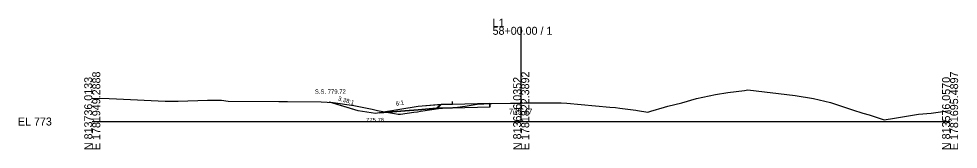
# Model space of a CAD drawing. Extents: x 5574 to 10203, y -10 to 9546.
# Drawn here: x 6574.3 to 6902.8, y 4990.3 to 5036 of the extents above; entities that cross this region are included whole.
import ezdxf

# ---------------------------------------------------------------- set-up
doc = ezdxf.new("R2010")
doc.units = 0
for name, color, linetype in [('Exist Cross Section Cell', 7, 'Continuous'), ('Exist XS Center Line Elevation Label', 7, 'Continuous'), ('Exist XS Ground Line', 7, 'Continuous'), ('Prop XS Ditch Slope Text', 7, 'Continuous'), ('Prop XS Ditch Standard Text', 7, 'Continuous'), ('Prop XS Dump Level', 7, 'Continuous'), ('Prop XS Earthwork Shape', 7, 'Continuous'), ('Prop XS EOT Tick Mark', 7, 'Continuous'), ('Prop XS Finish Grade', 7, 'Continuous'), ('Prop XS Finish Grade Earthwork', 7, 'Continuous'), ('Prop XS Finish Grade Paved Shoulder', 7, 'Continuous'), ('Prop XS Finish Grade Pavement', 7, 'Continuous'), ('Prop XS Hydro Typical Ditch Data', 7, 'Continuous'), ('Prop XS Pvmt Edge Slope', 7, 'Continuous'), ('Prop XS Side Slope Text', 7, 'Continuous'), ('Prop XS SS Elevation Text', 7, 'Continuous'), ('Prop XS Subgrade Earthwork', 7, 'Continuous'), ('Scratch_Level_3', 7, 'Continuous'), ('Scratch_Level_6', 7, 'Continuous')]:
    doc.layers.add(name, color=color, linetype=linetype)

msp = doc.modelspace()

# ---------------------------------------------------------------- linework, layer by layer
at = {"layer": 'Exist Cross Section Cell'}
for p, q in [((6750, 5000), (6750, 5033.15)), ((6600, 5000), (6750, 5000)), ((6750, 5000), (6900, 5000))]:
    msp.add_line(p, q, dxfattribs=at)
at = {"layer": 'Exist XS Ground Line'}
for p, q in [((6817.97, 5009.47), (6822.32, 5010.16)), ((6822.32, 5010.16), (6828.1, 5010.9)), ((6828.1, 5010.9), (6829.32, 5011.05)), ((6829.32, 5011.05), (6845.79, 5009.06)), ((6600, 5008.19), (6605.92, 5008.04)), ((6605.92, 5008.04), (6608.43, 5007.98)), ((6608.43, 5007.98), (6625.47, 5007.18)), ((6625.47, 5007.18), (6626.99, 5007.13)), ((6626.99, 5007.13), (6630.07, 5007.14)), ((6630.07, 5007.14), (6640.36, 5007.46)), ((6640.36, 5007.46), (6645.15, 5007.52)), ((6645.15, 5007.52), (6647.5, 5007.09)), ((6647.5, 5007.09), (6665.26, 5007.01)), ((6665.26, 5007.01), (6666.44, 5007.05)), ((6666.44, 5007.05), (6668.25, 5007.02)), ((6668.25, 5007.02), (6680.11, 5006.87)), ((6680.11, 5006.87), (6684.29, 5006.66)), ((6806.16, 5006.49), (6811.29, 5008.09)), ((6811.29, 5008.09), (6817.97, 5009.47)), ((6845.79, 5009.06), (6852.25, 5008)), ((6852.25, 5008), (6858.23, 5006.6)), ((6684.29, 5006.66), (6691.47, 5005.56)), ((6691.47, 5005.56), (6697.88, 5004.27)), ((6697.88, 5004.27), (6699.75, 5003.9)), ((6699.75, 5003.9), (6702.88, 5003.3)), ((6713.78, 5003.44), (6714.77, 5003.59)), ((6714.77, 5003.59), (6721.93, 5004.63)), ((6721.93, 5004.63), (6724.32, 5004.77)), ((6724.32, 5004.77), (6727.71, 5005.03)), ((6727.71, 5005.03), (6730.42, 5005.42)), ((6730.42, 5005.42), (6734.63, 5006.03)), ((6734.63, 5006.03), (6736.99, 5006.14)), ((6736.99, 5006.14), (6739.04, 5006.25)), ((6739.04, 5006.25), (6746.32, 5006.39)), ((6746.32, 5006.39), (6750, 5006.47)), ((6750, 5006.47), (6751.03, 5006.49)), ((6751.03, 5006.49), (6755.57, 5006.52)), ((6755.57, 5006.52), (6762.28, 5006.57)), ((6762.28, 5006.57), (6763.98, 5006.5)), ((6763.98, 5006.5), (6765.96, 5006.41)), ((6765.96, 5006.41), (6780.97, 5005.04)), ((6780.97, 5005.04), (6782.95, 5004.85)), ((6782.95, 5004.85), (6784.5, 5004.65)), ((6784.5, 5004.65), (6790.1, 5003.92)), ((6790.1, 5003.92), (6790.71, 5003.82)), ((6790.71, 5003.82), (6794.29, 5003.3)), ((6794.29, 5003.3), (6795.29, 5003.64)), ((6795.29, 5003.64), (6800.12, 5005.06)), ((6800.12, 5005.06), (6801.27, 5005.35)), ((6801.27, 5005.35), (6806.16, 5006.49)), ((6858.23, 5006.6), (6865.9, 5004.08)), ((6865.9, 5004.08), (6869.47, 5002.98)), ((6895.81, 5003.26), (6900, 5003.81)), ((6702.88, 5003.3), (6705.75, 5002.77)), ((6705.75, 5002.77), (6707.03, 5002.52)), ((6707.03, 5002.52), (6707.75, 5002.57)), ((6707.75, 5002.57), (6712.41, 5003.25)), ((6712.41, 5003.25), (6713.78, 5003.44)), ((6869.47, 5002.98), (6871.73, 5002.34)), ((6871.73, 5002.34), (6874.5, 5001.42)), ((6874.5, 5001.42), (6876.91, 5000.57)), ((6876.91, 5000.57), (6880.59, 5001.22)), ((6880.59, 5001.22), (6888.96, 5002.63)), ((6888.96, 5002.63), (6893.41, 5002.98)), ((6893.41, 5002.98), (6895.81, 5003.26))]:
    msp.add_line(p, q, dxfattribs=at)
at = {"layer": 'Prop XS Dump Level'}
msp.add_line((6739.04, 5006.25), (6726, 5005.99), dxfattribs=at)
msp.add_line((6739.04, 5006.25), (6726, 5005.99), dxfattribs=at)
at = {"layer": 'Prop XS Earthwork Shape'}
for points in [[(6700.46, 5003.03), (6699, 5002.78), (6693, 5003.78), (6683.09, 5006.72), (6684.29, 5006.66), (6691.47, 5005.56), (6697.88, 5004.27), (6699.75, 5003.9), (6702.88, 5003.3), (6703.18, 5003.24)], [(6714, 5004.11), (6703.18, 5003.24), (6705.75, 5002.77), (6707.03, 5002.52), (6707.75, 5002.57), (6712.41, 5003.25), (6713.78, 5003.44), (6714.77, 5003.59), (6721.93, 5004.63), (6722.46, 5004.66), (6721.63, 5004.64), (6720.35, 5004.62)], [(6726, 5004.73), (6722.46, 5004.66), (6724.32, 5004.77), (6727.71, 5005.03), (6730.42, 5005.42), (6734.63, 5006.03), (6736.99, 5006.14), (6739.04, 5006.25), (6739.04, 5005)]]:
    msp.add_lwpolyline(points, close=True, dxfattribs=at)
at = {"layer": 'Prop XS EOT Tick Mark'}
msp.add_line((6726, 5005.98), (6726, 5006.98), dxfattribs=at)
at = {"layer": 'Prop XS Finish Grade'}
for p, q in [((6714, 5005.26), (6700.46, 5003)), ((6722, 5005.9), (6714, 5005.26)), ((6722, 5005.9), (6721.62, 5005.87))]:
    msp.add_line(p, q, dxfattribs=at)
at = {"layer": 'Prop XS Finish Grade Earthwork'}
for p, q in [((6693, 5003.76), (6683, 5006.72)), ((6699, 5002.76), (6693, 5003.76)), ((6700.46, 5003), (6699, 5002.76))]:
    msp.add_line(p, q, dxfattribs=at)
at = {"layer": 'Prop XS Finish Grade Paved Shoulder'}
msp.add_line((6726, 5005.98), (6722, 5005.9), dxfattribs=at)
at = {"layer": 'Prop XS Finish Grade Pavement'}
msp.add_line((6739.04, 5006.25), (6726, 5005.98), dxfattribs=at)
at = {"layer": 'Prop XS Hydro Typical Ditch Data'}
for p, q in [((6693, 5003.76), (6683, 5006.72)), ((6699, 5002.76), (6693, 5003.76)), ((6714, 5005.26), (6699, 5002.76))]:
    msp.add_line(p, q, dxfattribs=at)
at = {"layer": 'Prop XS Pvmt Edge Slope'}
msp.add_line((6722, 5005.9), (6720.72, 5004.63), dxfattribs=at)
at = {"layer": 'Prop XS Subgrade Earthwork'}
for p, q in [((6714.37, 5004.12), (6700.46, 5003)), ((6720.72, 5004.63), (6714.37, 5004.12)), ((6721.63, 5004.64), (6720.72, 5004.63)), ((6726, 5004.73), (6721.63, 5004.64)), ((6739.04, 5005), (6726, 5004.73)), ((6739.04, 5005), (6739.04, 5006.25))]:
    msp.add_line(p, q, dxfattribs=at)
at = {"layer": 'Scratch_Level_3'}
for p, q in [((6714, 5005.28), (6700.46, 5003.03)), ((6700.46, 5003.03), (6714, 5004.11)), ((6721.25, 5005.86), (6714, 5005.28)), ((6714, 5004.11), (6720.35, 5004.62)), ((6720.35, 5004.62), (6721.63, 5005.89)), ((6721.63, 5005.89), (6721.25, 5005.86))]:
    msp.add_line(p, q, dxfattribs=at)
at = {"layer": 'Scratch_Level_6'}
for points in [[(6726, 5004.73), (6722.46, 5004.66), (6724.32, 5004.77), (6727.71, 5005.03), (6730.42, 5005.42), (6734.63, 5006.03), (6736.99, 5006.14), (6739.04, 5006.25), (6739.04, 5005)], [(6702.88, 5003.3), (6703.27, 5003.23), (6700.46, 5003), (6702.58, 5003.36)]]:
    msp.add_lwpolyline(points, close=True, dxfattribs=at)

# ---------------------------------------------------------------- texts
at = {"layer": 'Exist Cross Section Cell'}
for s, p in [('58+00.00 / 1', (6740, 5030.35)), ('L1', (6740, 5033.15)), ('EL 773', (6574, 4998.6))]:
    msp.add_text(s, height=2.8, dxfattribs=at).set_placement(p)
for s, p in [('E 1781949.2888', (6602.8, 4990)), ('E 1781822.3892', (6752.8, 4990)), ('E 1781695.4897', (6902.8, 4990)), ('N 813736.0133', (6600, 4990)), ('N 813656.0352', (6750, 4990)), ('N 813576.0570', (6900, 4990))]:
    msp.add_text(s, height=2.8, rotation=90, dxfattribs=at).set_placement(p)
at = {"layer": 'Exist XS Center Line Elevation Label'}
msp.add_text('779.47', height=2, dxfattribs=at).set_placement((6745.7, 5002.47))
at = {"layer": 'Prop XS Ditch Slope Text'}
msp.add_text('6:1', height=1.5, rotation=9.4623, dxfattribs=at).set_placement((6706.25, 5005.51))
at = {"layer": 'Prop XS Ditch Standard Text'}
msp.add_text('775.76', height=1.5, dxfattribs=at).set_placement((6695.74, 4999.78))
at = {"layer": 'Prop XS Dump Level'}
for s, height, p in [('Case4', 0.04, (6714, 5005.24)), ('Eop', 0.3, (6739.04, 5005.95))]:
    msp.add_text(s, height=height, dxfattribs=at).set_placement(p)
at = {"layer": 'Prop XS Side Slope Text'}
msp.add_text('3.38:1', height=1.5, rotation=343.497, dxfattribs=at).set_placement((6685.84, 5007.45))
at = {"layer": 'Prop XS SS Elevation Text'}
msp.add_text('S.S. 779.72', height=1.5, dxfattribs=at).set_placement((6677.85, 5009.72))

doc.saveas('drawing.dxf')
